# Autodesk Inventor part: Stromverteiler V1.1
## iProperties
Created: 2018-06
Part Number: Stromverteiler V1.1
Material: Standard
Document SubType Name: Blech
Designer: Acer
Density: 1 g/cm^3
Sheet Metal Rule: Standard_mm
Author: Acer
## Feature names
1. Extrusion1
2. Extrusion2
3. Extrusion3
4. Extrusion4
5. Fase2 [Chamfer]
